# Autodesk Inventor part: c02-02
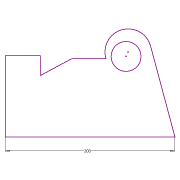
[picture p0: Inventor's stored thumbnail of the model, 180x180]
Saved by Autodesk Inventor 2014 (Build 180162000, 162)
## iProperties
Created: 2013-02
Part Number: c02-02
Material: Generic
Document SubType Name: Modeling
Designer: Thom Tremblay
Density: 1 g/cm^3
Appearance: Default
Author: Thom Tremblay
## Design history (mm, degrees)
sketch "Sketch1"
  geometry: L1 (115.304, -55.869)-(86.562, 51.397); L2 (-84.696, 39.97)-(-84.696, -55.869); L3 (-84.696, -55.869)-(115.304, -55.869); L4 (-43.342, 39.97)-(-43.342, 16.589); L5 (33.936, 36.433)-(-6.543, 36.433); L6 (-43.342, 39.97)-(-84.696, 39.97); L7 (-43.342, 16.589)-(-6.543, 36.433); C1 r 17.66 at (57.64, 39.118); A1 r 27.359 centre (60.135, 44.316) between (86.562, 51.397) and (33.936, 36.433)
  constraints: 14 end point, 2 centre point, 2 parallel, 2 perpendicular, 2 point on circle, 1 tangent, 1 vertical
  dimensions: "d0" = 200 dimension on L1 L2.start L2.end L2 L1.start L3 L4.start L4.end L4 L5.end A1.centre A1 L1.end L5.start L5 L6 C1.centre C1 L7; "d0" = 200 distance of L2.end L1.start
